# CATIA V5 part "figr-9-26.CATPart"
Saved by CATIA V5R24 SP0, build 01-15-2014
Part number: Part1
Bounding box of the stored display mesh (mm): x -75 to 75, y -50 to 50, z 0 to 40
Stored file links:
  D:\KAVITA\CATIA V5-6R2014 Project_ Kavita\CATIA V5-6R2014_partfiles\Partfiles\c09_catia_v5-6r2014_prt\figr-9-26.CATPart
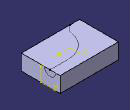
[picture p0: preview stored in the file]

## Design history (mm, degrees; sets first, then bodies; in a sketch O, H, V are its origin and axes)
Body1 (main body)
  Sketch1 on xy-plane, origin (0, 0, 0), H (1, 0, 0), V (0, 1, 0)
    line L1 (-75, 50) -> (75, 50)
    line L2 (75, 50) -> (75, -50)
    line L3 (75, -50) -> (-75, -50)
    line L4 (-75, -50) -> (-75, 50)
    axis line L5 (75, -50) -> (-75, 50)
    length L2 = 100
    length L3 = 150
    horizontal: L1 H, L3 H
    vertical: L2 V, L4 V
    midpoint: O L5
  Pad1: profile Sketch1, direction (0, 0, 1), length 40
  Sketch2 on face of Pad1, origin (75, 0, 0), H (0, 1, 0), V (0, 0, 1)
    arc A1 centre (24.1478, 40) radius 14.6047 from (9.543, 40) to (38.7525, 40) ccw
    point P1 (24.1478, 40)
    reference projected point E1 (24.1478, 40) from vertex of Sketch3
    line L1 (9.543, 40) -> (38.7525, 40)
    coincidence: P1 E1
    horizontal: L1 H
  Sketch3 on face of Pad1, origin (0, 0, 40), H (1, 0, 0), V (0, 1, 0)
    point P1 (75, 24.1478)
    line L1 (75, 24.1478) -> (28.6577, 24.1478)
    arc A1 centre (28.6577, -39.2062) radius 63.354 from (28.6577, 24.1478) to (-33.8383, -28.8149) ccw
    arc A2 centre (-62.192, -24.1005) radius 28.7429 from (-33.8383, -28.8149) to (-49.7271, -50) cw
    point P6 (-49.7271, -50)
    reference projected line E1 (75, -50) -> (75, 50) from edge [face of Pad1 | face of Pad1]
    reference projected line E2 (-75, -50) -> (75, -50) from edge [face of Pad1 | face of Pad1]
    horizontal: L1 H
    tangency: A1 L1, A2 A1
    coincidence: P1 E1, P6 E2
